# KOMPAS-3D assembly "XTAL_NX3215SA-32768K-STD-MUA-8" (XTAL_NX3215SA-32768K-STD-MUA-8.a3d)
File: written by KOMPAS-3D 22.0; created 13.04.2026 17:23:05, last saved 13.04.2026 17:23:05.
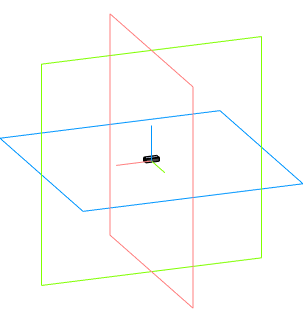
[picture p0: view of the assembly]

Document properties: Автор: Andrey; Полное имя файла: C:\Users\User1\Documents\XTAL_NX3215SA-32768K-STD-MUA-8.a3d

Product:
- Component [detail]: NX3215SA-32.768K-STD-MUA-8  | qty 1  | source file: NX3215SA-32.768K-STD-MUA-8.m3d
- Part/product: XTAL_NX3215SA-32768K-STD-MUA-8
    Комментарий: XTAL_NX3215SA-32768K-STD-MUA-8

Referenced files in C:\Users\User1\Documents\: NX3215SA-32.768K-STD-MUA-8.m3d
